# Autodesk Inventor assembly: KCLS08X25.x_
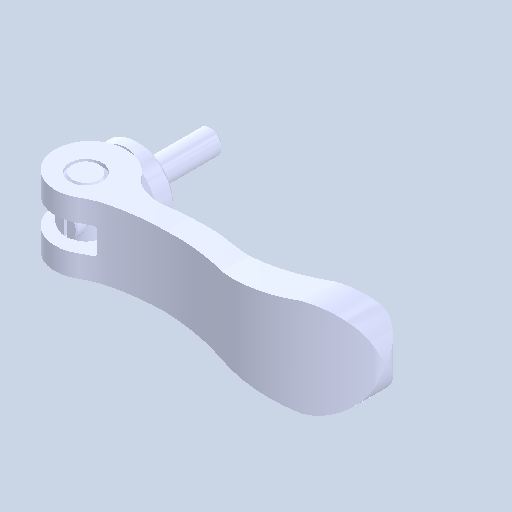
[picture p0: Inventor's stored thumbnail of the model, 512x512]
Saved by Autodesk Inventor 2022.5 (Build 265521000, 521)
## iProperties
Created: 2024-08
Part Number: KCLS08X25.x_
Document SubType Name: Assembly
Designer: ImaoCorp
Author: ImaoCorp
Sending System: SOLIDWORKS 2022-2022290
MC: AMD64
MC_MODEL: Intel64 Family 6 Model 60 Stepping 3, GenuineIntel
OS: Windows_NT
FRU: Parasolid Version 33.1, build 260,  4-25-2022
FORMAT: text
GUISE: transmit
KEY: FILEKCLS08X25.x_t
DATE: Thu Aug 29 10:55:05 2024
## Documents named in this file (5)
- Y:\5.更新分\2024年対応\1001_KCL\データ\kcls08x25\KCLS08X25.x_.iam
- Y:\5.更新分\2024年対応\1001_KCL\データ\kcls08x25\KCLS08X25_01.ipt
- Y:\5.更新分\2024年対応\1001_KCL\データ\kcls08x25\KCLS08X25_02.ipt
- Y:\5.更新分\2024年対応\1001_KCL\データ\kcls08x25\KCLS08X25_03.ipt
- Y:\5.更新分\2024年対応\1001_KCL\データ\kcls08x25\KCLS08X25_04.ipt
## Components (4 placed, 4 different names)
1. KCLS08X25_01
2. KCLS08X25_02
3. KCLS08X25_03
4. KCLS08X25_04
